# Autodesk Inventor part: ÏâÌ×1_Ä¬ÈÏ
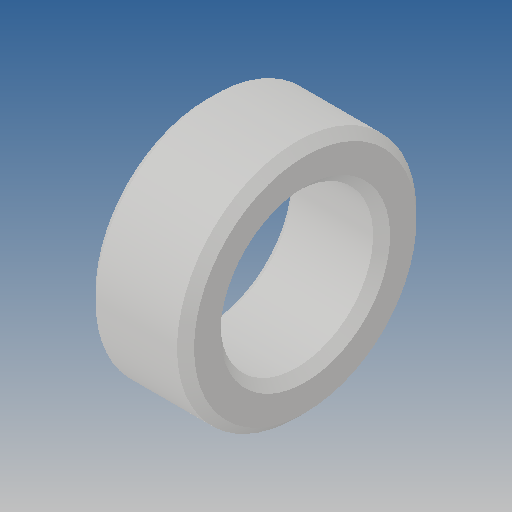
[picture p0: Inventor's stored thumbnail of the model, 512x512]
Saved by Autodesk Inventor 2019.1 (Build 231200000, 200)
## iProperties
Created: 2012-10
Part Number: ÏâÌ×1_Ä¬ÈÏ
Material: Ogólny
Document SubType Name: Modeling
Designer: CADENGINEERING4
Density: 1 g/cm^3
Appearance: Domyślna
Author: CADENGINEERING4
Revision Number: ÈÎºÎ
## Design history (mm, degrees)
feature "NONE"
node "Bryła1"
